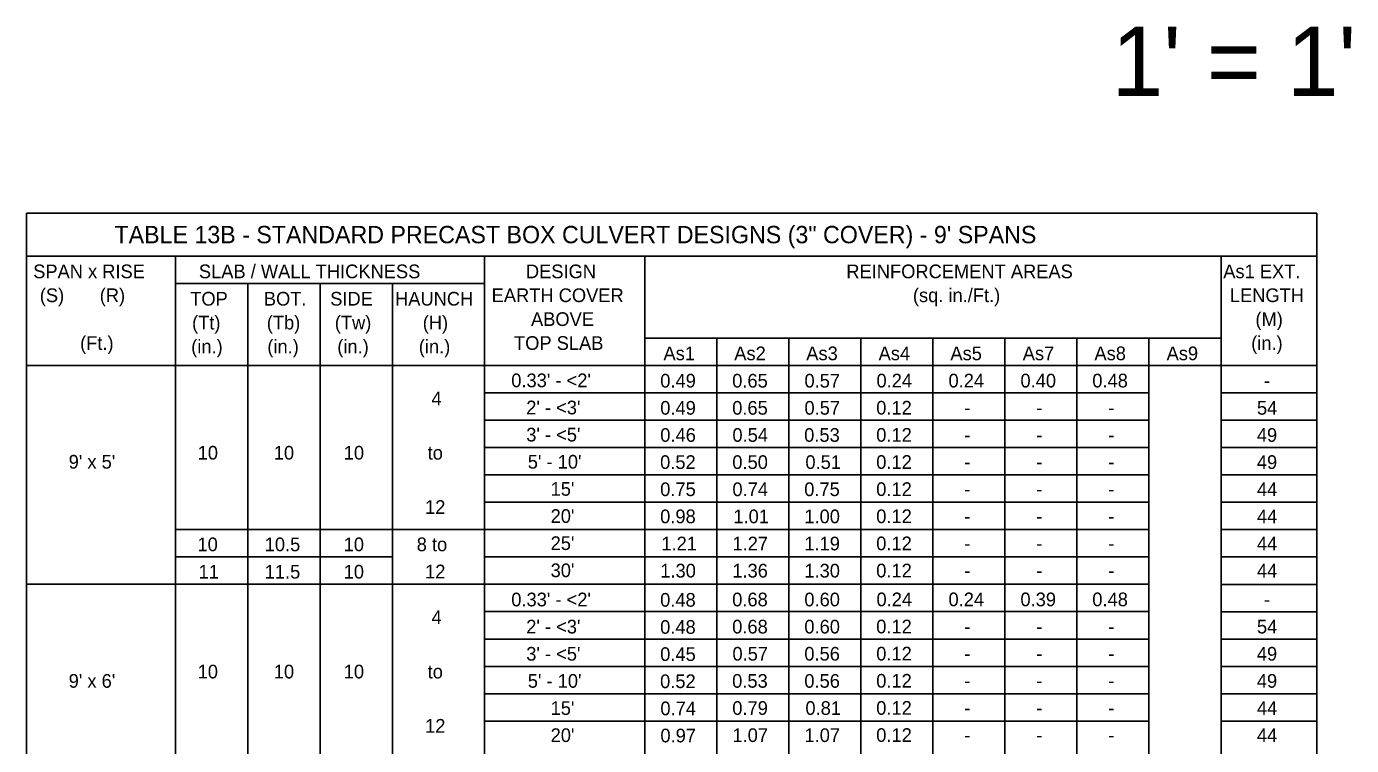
# Model space of a CAD drawing. Extents: x 10346.98 to 10349.19, y 76371.36 to 76372.62.
# Drawn here: x 10347.625 to 10348.236, y 76372.289 to 76372.621 of the extents above; entities that cross this region are included whole.
import ezdxf

# ---------------------------------------------------------------- set-up
doc = ezdxf.new("R2010")
doc.units = 0
doc.layers.add('AdhocPoint_dp', color=7, linetype='Continuous')
doc.layers.add('PlotBorder_dp', color=7, linetype='Continuous')

msp = doc.modelspace()

# ---------------------------------------------------------------- linework, layer by layer
at = {"layer": 'PlotBorder_dp'}
for p, q in [((10347.62504, 76372.53475), (10347.62504, 76371.96053)), ((10347.62504, 76372.53475), (10348.21977, 76372.53475)), ((10348.21977, 76372.53475), (10348.21977, 76371.96053)), ((10347.62504, 76372.51488), (10348.21977, 76372.51488)), ((10347.69367, 76372.51488), (10347.69367, 76371.96053)), ((10347.83612, 76372.51488), (10347.83612, 76371.96053)), ((10347.91, 76372.51488), (10347.91, 76371.96053)), ((10348.17559, 76372.51488), (10348.17559, 76371.96053)), ((10347.69367, 76372.50228), (10347.83612, 76372.50228)), ((10347.72703, 76372.50228), (10347.72703, 76371.96053)), ((10347.76039, 76372.50228), (10347.76039, 76371.96053)), ((10347.79375, 76372.50228), (10347.79375, 76371.96053)), ((10347.91, 76372.47713), (10348.17559, 76372.47713)), ((10347.9432, 76372.47713), (10347.9432, 76371.96053)), ((10347.97639, 76372.47713), (10347.97639, 76371.96053)), ((10348.00959, 76372.47713), (10348.00959, 76371.96053)), ((10348.04279, 76372.47713), (10348.04279, 76371.96053)), ((10348.07599, 76372.47713), (10348.07599, 76371.96053)), ((10348.07599, 76372.47713), (10348.07599, 76371.96053)), ((10348.10919, 76372.47713), (10348.10919, 76371.96053)), ((10348.14239, 76372.47713), (10348.14239, 76371.96053)), ((10347.62504, 76372.46453), (10348.21977, 76372.46453)), ((10347.83612, 76372.45193), (10348.14239, 76372.45193)), ((10348.17559, 76372.45191), (10348.21977, 76372.45191)), ((10347.83612, 76372.43933), (10348.14239, 76372.43933)), ((10348.17559, 76372.43931), (10348.21977, 76372.43931)), ((10347.83612, 76372.42673), (10348.14239, 76372.42673)), ((10348.17559, 76372.42671), (10348.21977, 76372.42671)), ((10347.83612, 76372.41413), (10348.14239, 76372.41413)), ((10348.17559, 76372.41411), (10348.21977, 76372.41411)), ((10347.83612, 76372.40153), (10348.14239, 76372.40153)), ((10348.17559, 76372.40151), (10348.21977, 76372.40151)), ((10347.83612, 76372.38893), (10347.69367, 76372.38893)), ((10347.83612, 76372.38893), (10348.14239, 76372.38893)), ((10348.17559, 76372.38891), (10348.21977, 76372.38891)), ((10347.79375, 76372.37633), (10347.69367, 76372.37633)), ((10347.83612, 76372.37633), (10348.14239, 76372.37633)), ((10348.17559, 76372.37631), (10348.21977, 76372.37631)), ((10347.62504, 76372.36373), (10348.14239, 76372.36373)), ((10348.17559, 76372.36371), (10348.21977, 76372.36371)), ((10347.83612, 76372.35113), (10348.14239, 76372.35113)), ((10348.17559, 76372.35111), (10348.21977, 76372.35111)), ((10347.83612, 76372.33853), (10348.14239, 76372.33853)), ((10348.17559, 76372.33851), (10348.21977, 76372.33851)), ((10347.83612, 76372.32593), (10348.14239, 76372.32593)), ((10348.17559, 76372.32591), (10348.21977, 76372.32591)), ((10347.83612, 76372.31333), (10348.14239, 76372.31333)), ((10348.17559, 76372.31331), (10348.21977, 76372.31331)), ((10347.83612, 76372.30073), (10348.14239, 76372.30073)), ((10348.17559, 76372.30071), (10348.21977, 76372.30071))]:
    msp.add_line(p, q, dxfattribs=at)

# ---------------------------------------------------------------- texts
at = {"layer": 'AdhocPoint_dp'}
for s, height, p in [("1' = 1'", 0.032, (10348.12518, 76372.58867)), ('TABLE 13B - STANDARD PRECAST BOX CULVERT DESIGNS (3" COVER) - 9\' SPANS', 0.008, (10347.66557, 76372.52082)), ('SLAB / WALL THICKNESS', 0.0063, (10347.70449, 76372.50472)), ('As1', 0.0063, (10347.91862, 76372.46696)), ('As2', 0.0063, (10347.95125, 76372.46696)), ('As3', 0.0063, (10347.98444, 76372.46696)), ('As4', 0.0063, (10348.01777, 76372.46696)), ('As5', 0.0063, (10348.05087, 76372.46696)), ('As7', 0.0063, (10348.08421, 76372.46696)), ('As8', 0.0063, (10348.11726, 76372.46696)), ('As9', 0.0063, (10348.15051, 76372.46696)), ('10', 0.0063, (10347.70384, 76372.37898)), ('10.5', 0.0063, (10347.73483, 76372.37898)), ('10', 0.0063, (10347.77122, 76372.37898)), ('8 to', 0.0063, (10347.80488, 76372.37898)), ('11', 0.0063, (10347.70435, 76372.36638)), ('11.5', 0.0063, (10347.73483, 76372.36638)), ('10', 0.0063, (10347.77122, 76372.36638)), ('12', 0.0063, (10347.80874, 76372.36648))]:
    msp.add_text(s, height=height, dxfattribs=at).set_placement(p)
at = {"layer": 'PlotBorder_dp'}
for s, p in [('SPAN x RISE', (10347.62812, 76372.50472)), ('DESIGN', (10347.85522, 76372.50472)), ('REINFORCEMENT AREAS', (10348.0029, 76372.50472)), ('(S)       (R)', (10347.63117, 76372.49372)), ('(sq. in./Ft.)', (10348.03359, 76372.49372)), ('TOP', (10347.70049, 76372.49212)), ('BOT.', (10347.73443, 76372.49212)), ('SIDE', (10347.76502, 76372.49212)), ('HAUNCH', (10347.79491, 76372.49212)), ('EARTH COVER', (10347.83943, 76372.49372)), ('ABOVE', (10347.85757, 76372.48272)), ('(Tt)', (10347.70134, 76372.48112)), ('(Tb)', (10347.73577, 76372.48112)), ('(Tw)', (10347.76713, 76372.48112)), ('(H)', (10347.80766, 76372.48112)), ('(Ft.)', (10347.64974, 76372.47172)), ('(in.)', (10347.70095, 76372.47012)), ('(in.)', (10347.73604, 76372.47012)), ('(in.)', (10347.76828, 76372.47012)), ('(in.)', (10347.80585, 76372.47012)), ('TOP SLAB', (10347.84974, 76372.47172)), ("0.33' - <2'", (10347.84847, 76372.45452)), ('0.49', (10347.91714, 76372.45436)), ('0.65', (10347.9503, 76372.45436)), ('0.57', (10347.98361, 76372.45436)), ('0.24', (10348.0168, 76372.45441)), ('0.24', (10348.04999, 76372.45441)), ('0.40', (10348.08315, 76372.45441)), ('0.48', (10348.11627, 76372.45441)), ('4', (10347.8117, 76372.44618)), ("2' - <3'", (10347.85537, 76372.44202)), ('0.49', (10347.91714, 76372.44186)), ('0.65', (10347.9503, 76372.44186)), ('0.57', (10347.98361, 76372.44186)), ('0.12', (10348.01668, 76372.44191)), ('-', (10348.05726, 76372.44191)), ('-', (10348.09047, 76372.44191)), ('-', (10348.12366, 76372.44191)), ("3' - <5'", (10347.85537, 76372.42952)), ('0.46', (10347.91714, 76372.42936)), ('0.54', (10347.9504, 76372.42936)), ('0.53', (10347.98347, 76372.42936)), ('0.12', (10348.01668, 76372.42941)), ('10', (10347.70392, 76372.42118)), ('10', (10347.73901, 76372.42118)), ('10', (10347.77125, 76372.42118)), ('to', (10347.80992, 76372.42118)), ('-', (10348.05726, 76372.42941)), ('-', (10348.09047, 76372.42941)), ('-', (10348.12366, 76372.42941)), ("9' x 5'", (10347.64447, 76372.41702)), ("5' - 10'", (10347.85608, 76372.41702)), ('0.52', (10347.91707, 76372.41686)), ('0.50', (10347.95035, 76372.41686)), ('0.51', (10347.98404, 76372.41686)), ('0.12', (10348.01668, 76372.41691)), ('-', (10348.05726, 76372.41691)), ('-', (10348.09047, 76372.41691)), ('-', (10348.12366, 76372.41691)), ("15'", (10347.8666, 76372.40452)), ('0.75', (10347.9171, 76372.40436)), ('0.74', (10347.9504, 76372.40436)), ('0.75', (10347.9835, 76372.40436)), ('0.12', (10348.01668, 76372.40441)), ('-', (10348.05726, 76372.40441)), ('-', (10348.09047, 76372.40441)), ('-', (10348.12366, 76372.40441)), ('12', (10347.80874, 76372.39618)), ("20'", (10347.8666, 76372.39202)), ('0.98', (10347.91709, 76372.39186)), ('1.01', (10347.95084, 76372.39186)), ('1.00', (10347.98355, 76372.39186)), ('0.12', (10348.01668, 76372.39191)), ('-', (10348.05726, 76372.39191)), ('-', (10348.09047, 76372.39191)), ('-', (10348.12366, 76372.39191)), ("25'", (10347.8666, 76372.37952)), ('1.21', (10347.91764, 76372.37936)), ('1.27', (10347.95041, 76372.37936)), ('1.19', (10347.98354, 76372.37936)), ('0.12', (10348.01668, 76372.37941)), ('-', (10348.05726, 76372.37941)), ('-', (10348.09047, 76372.37941)), ('-', (10348.12366, 76372.37941)), ("30'", (10347.8666, 76372.36702)), ('1.30', (10347.91715, 76372.36686)), ('1.36', (10347.95034, 76372.36686)), ('1.30', (10347.98355, 76372.36686)), ('0.12', (10348.01668, 76372.36691)), ('-', (10348.05726, 76372.36691)), ('-', (10348.09047, 76372.36691)), ('-', (10348.12366, 76372.36691)), ("0.33' - <2'", (10347.84847, 76372.35358)), ('0.68', (10347.95029, 76372.35358)), ('0.60', (10347.98355, 76372.35358)), ('0.24', (10348.0168, 76372.35363)), ('0.24', (10348.04999, 76372.35363)), ('0.39', (10348.08314, 76372.35363)), ('0.48', (10348.11627, 76372.35363)), ('0.48', (10347.91709, 76372.35342)), ('-', (10348.19536, 76372.35358)), ('4', (10347.8117, 76372.34538)), ("2' - <3'", (10347.85537, 76372.34108)), ('0.48', (10347.91709, 76372.34092)), ('0.68', (10347.95029, 76372.34108)), ('0.60', (10347.98355, 76372.34108)), ('0.12', (10348.01668, 76372.34113)), ('-', (10348.05726, 76372.34113)), ('-', (10348.09047, 76372.34113)), ('-', (10348.12366, 76372.34113)), ('54', (10348.19216, 76372.34108)), ("3' - <5'", (10347.85537, 76372.32858)), ('0.45', (10347.9171, 76372.32842)), ('0.57', (10347.95041, 76372.32858)), ('0.56', (10347.98354, 76372.32858)), ('0.12', (10348.01668, 76372.32863)), ('-', (10348.05726, 76372.32863)), ('-', (10348.09047, 76372.32863)), ('-', (10348.12366, 76372.32863)), ('49', (10348.1921, 76372.32858)), ('10', (10347.70392, 76372.32038)), ('10', (10347.73901, 76372.32038)), ('10', (10347.77125, 76372.32038)), ('to', (10347.80992, 76372.32038)), ("9' x 6'", (10347.64447, 76372.31608)), ("5' - 10'", (10347.85608, 76372.31608)), ('0.52', (10347.91707, 76372.31592)), ('0.53', (10347.95027, 76372.31608)), ('0.56', (10347.98354, 76372.31608)), ('0.12', (10348.01668, 76372.31613)), ('-', (10348.05726, 76372.31613)), ('-', (10348.09047, 76372.31613)), ('-', (10348.12366, 76372.31613)), ('49', (10348.1921, 76372.31608)), ("15'", (10347.8666, 76372.30358)), ('0.74', (10347.9172, 76372.30342)), ('0.79', (10347.95034, 76372.30358)), ('0.81', (10347.98404, 76372.30358)), ('0.12', (10348.01668, 76372.30363)), ('-', (10348.05726, 76372.30363)), ('-', (10348.09047, 76372.30363)), ('-', (10348.12366, 76372.30363)), ('44', (10348.19216, 76372.30358)), ('12', (10347.80874, 76372.29538)), ("20'", (10347.8666, 76372.29108)), ('0.97', (10347.91721, 76372.29092)), ('1.07', (10347.95041, 76372.29108)), ('1.07', (10347.98361, 76372.29108)), ('0.12', (10348.01668, 76372.29113)), ('-', (10348.05726, 76372.29113)), ('-', (10348.09047, 76372.29113)), ('-', (10348.12366, 76372.29113)), ('44', (10348.19216, 76372.29108))]:
    msp.add_text(s, height=0.0063, dxfattribs=at).set_placement(p)
for s, p in [('As1 EXT.', (10348.17663, 76372.50472)), ('LENGTH', (10348.17966, 76372.49372)), ('(M)', (10348.19146, 76372.48272)), ('(in.)', (10348.1895, 76372.47172)), ('-', (10348.19536, 76372.45436)), ('54', (10348.19216, 76372.44186)), ('49', (10348.1921, 76372.42936)), ('49', (10348.1921, 76372.41686)), ('44', (10348.19216, 76372.40436)), ('44', (10348.19216, 76372.39186)), ('44', (10348.19216, 76372.37936)), ('44', (10348.19216, 76372.36686))]:
    msp.add_text(s, height=0.0063, rotation=360, dxfattribs=at).set_placement(p)

doc.saveas('drawing.dxf')
